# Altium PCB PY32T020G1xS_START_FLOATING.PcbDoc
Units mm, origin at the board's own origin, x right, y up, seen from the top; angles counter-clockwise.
Board outline 150 x 47.08 mm, 2 copper layers (Top Layer, Bottom Layer); 56 components, 46 nets, 145 pads, 14 vias.
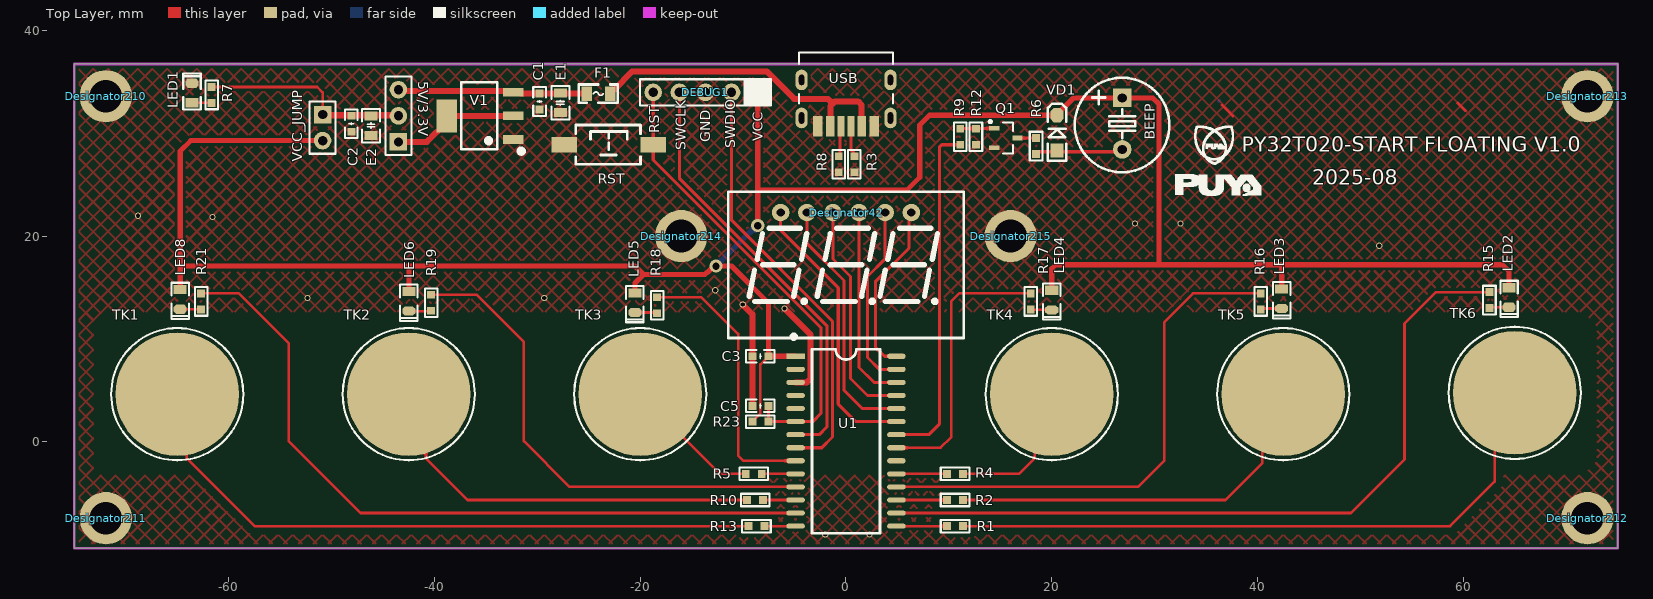
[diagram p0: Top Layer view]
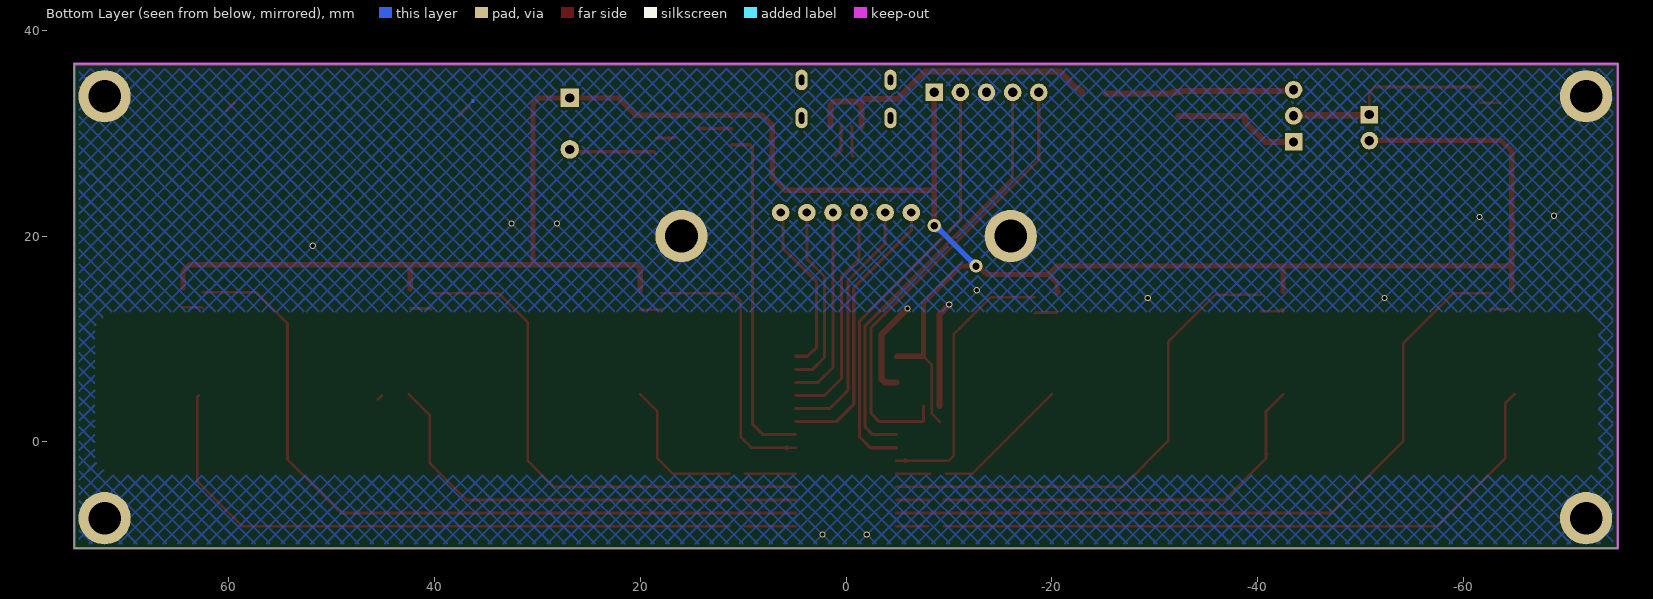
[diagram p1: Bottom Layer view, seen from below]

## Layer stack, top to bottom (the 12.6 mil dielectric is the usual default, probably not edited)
Top Solder: solder mask 0.0102, Solder Resist, Dk 3.5
Top Layer: signal copper 0.0356
Dielectric 1: dielectric 0.32, FR-4, Dk 4.8
Bottom Layer: signal copper 0.0356
Bottom Solder: solder mask 0.0102, Solder Resist, Dk 3.5

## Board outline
-74.993,-10.351 -74.993,36.728 75.006,36.728 75.006,-10.351

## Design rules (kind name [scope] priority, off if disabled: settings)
Clearance tk1 [InNet('NetR13_2')] p1: gap=0.7 ignorepadtopadclearanceinfootprint=FALSE
Clearance tk1_5 [InNet('NetR10_2')] p2: gap=0.7 ignorepadtopadclearanceinfootprint=FALSE
Clearance tk1_4 [InNet('NetR5_2')] p3: gap=0.7 ignorepadtopadclearanceinfootprint=FALSE
Clearance tk1_3 [InNet('NetR4_2')] p4: gap=0.7 ignorepadtopadclearanceinfootprint=FALSE
Clearance tk1_2 [InNet('NetR2_2')] p5: gap=0.7 ignorepadtopadclearanceinfootprint=FALSE
Clearance tk1_1 [InNet('NetR1_2')] p6: gap=0.7 ignorepadtopadclearanceinfootprint=FALSE
Clearance [All] p7: gap=0.254 ignorepadtopadclearanceinfootprint=FALSE
PlaneConnect [All] p1: planeconnectstyle=Direct reliefexpansion=0.508 reliefentries=4 reliefconductorwidth=0.254 reliefairgap=0.254
PolygonConnect [All] p1: connectstyle=Direct reliefconductorwidth=0.254 reliefentries=4 polygonreliefangle="90 Angle" airgapwidth=0.254
RoutingVias [All] p1: holewidth=0.711 width=1.27 viastyle="Through Hole" minholewidth=0.711 minwidth=1.27 maxholewidth=0.711 maxwidth=1.27
SolderMaskExpansion [All] p1: expansion=0.102 istentingtop=FALSE
Width [All] p1: maxlimit=0.6 minlimit=0.254 preferedwidth=0.254
29 further rules are at their usual default settings.

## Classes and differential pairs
component class "PY32T020_Touch Demo5_V1.1": 5V/3.3V BEEP C1 C2 C3 C5 DEBUG1 E1 E2 F1 LED1 LED2 LED3 LED4 LED5 LED6 LED8 Q1 R1 R2 R3 R4 R5 R6 R7 R8 R9 R10 R12 R13 R15 R16 R17 R18 R19 R21 R23 RST TK1 TK2 TK3 TK4 TK5 TK6 U1 USB V1 VCC_JUMP VD1

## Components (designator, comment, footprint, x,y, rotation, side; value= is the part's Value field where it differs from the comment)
5V/3.3V "HDR-1X3" HDR2.54-LI-3P -43.497,31.686 r90 top (schematic designator 1)
BEEP "DC5V" "BEEP 5x9x5.5" 26.86,30.924 r180 top (schematic designator BEEP1)
C1 "104" "C 0603_L" -29.781,33.084 r90 top
C2 "104" "C 0603_L" -48.069,30.924 r90 top
C3 "104" "C 0603_L" -8.319,8.319 r0 top
C5 "104" "C 0603_L" -8.319,3.492 r0 top
DEBUG1 "ISP" ISP_DIP_2.54_5P -8.572,33.972 r180 top
Designator42 "Comment" "SMG 0.36-3P" 0.006,17.209 r0 top
Designator210 "Comment" "M3 125X200"#1 -71.643,33.454 r0 top
Designator211 "Comment" "M3 125X200"#2 -72.024,-7.186 r0 top
Designator212 "Comment" "M3 125X200"#3 71.74,-7.059 r0 top
Designator213 "Comment" "M3 125X200"#4 71.486,33.454 r0 top
Designator214 "Comment" "M3 125X200"#5 -16.779,21.008 r0 top
Designator215 "Comment" "M3 125X200"#6 15.352,43.36 r0 top
E1 "10uF/10V" "C 0805_L" -27.749,32.956 r270 top
E2 "10uF/10V" "C 0805_L" -46.164,30.736 r270 top
F1 "500ma" "FU 0805" -24.066,33.846 r180 top
LED1 "红色" "LED 0805R" -63.564,33.912 r90 top
LED2 "红色" "LED 0805G" 64.453,14.034 r270 top
LED3 "红色" "LED 0805G" 42.355,13.906 r270 top
LED4 "红色" "LED 0805G" 20.002,13.779 r270 top
LED5 "红色" "LED 0805G" -20.511,13.525 r270 top
LED6 "红色" "LED 0805G" -42.481,13.652 r270 top
LED8 "红色" "LED 0805G" -64.706,13.84 r270 top
Q1 "SS8050" SOT23-3L 15.557,29.527 r270 top
R1 "4.3K" "R 0603_L" 10.604,-8.191 r0 top
R2 "4.3K" "R 0603_L" 10.604,-5.651 r0 top
R3 "5.1K" "R 0603_L" 0.826,26.987 r90 top
R4 "4.3K" "R 0603_L" 10.604,-3.111 r0 top
R5 "4.3K" "R 0603_L" -8.954,-3.111 r180 top
R6 "200R" "R 0603_L" 18.479,28.75 r270 top
R7 "1K" "R 0603_L" -61.658,33.718 r90 top
R8 "5.1K" "R 0603_L" -0.699,26.987 r90 top
R9 "1K" "R 0603_L" 11.112,29.654 r270 top
R10 "4.3K" "R 0603_L" -8.826,-5.651 r180 top
R12 "10K" "R 0603_L" 12.636,29.654 r90 top
R13 "4.3K" "R 0603_L" -8.7,-8.191 r180 top
R15 "1K" "R 0603_L" 62.547,13.779 r90 top
R16 "1K" "R 0603_L" 40.322,13.652 r90 top
R17 "1K" "R 0603_L" 17.97,13.652 r90 top
R18 "1K" "R 0603_L" -18.351,13.271 r90 top
R19 "1K" "R 0603_L" -40.322,13.525 r90 top
R21 "1K" "R 0603_L" -62.674,13.652 r90 top
R23 "10K" "R 0603_L" -8.319,1.968 r180 top
RST "6x6x5" "TSW SMD-3*6*5" -23.05,28.892 r0 top (schematic designator RST1)
TK1 "Touch 10X10mm" Touch-12X12mm -64.993,4.635 r0 top (schematic designator Th7)
TK2 "Touch 10X10mm" Touch-12X12mm -42.494,4.635 r0 top (schematic designator Th5)
TK3 "Touch 10X10mm" Touch-12X12mm -19.994,4.635 r0 top (schematic designator Th4)
TK4 "Touch 10X10mm" Touch-12X12mm 20.007,4.635 r0 top (schematic designator Th3)
TK5 "Touch 10X10mm" Touch-12X12mm 42.506,4.635 r0 top (schematic designator Th2)
TK6 "Touch 10X10mm" Touch-12X12mm 65.006,4.763 r0 top (schematic designator Th1)
U1 "PY32T020G16" SOP28_L 0.006,0.064 r0 top
USB "USB-C" USB-C/S_C 0.006,37.728 r180 top (schematic designator USB_POWER1)
V1 "AMS1117-3V3" SOT223_N -35.623,31.686 r90 top
VCC_JUMP "HDR-1X2" HDR2.54-LI-2P -50.863,30.543 r270 top (schematic designator VCC_JUMP1)
VD1 "A7" SOD-123 20.511,30.035 r90 top

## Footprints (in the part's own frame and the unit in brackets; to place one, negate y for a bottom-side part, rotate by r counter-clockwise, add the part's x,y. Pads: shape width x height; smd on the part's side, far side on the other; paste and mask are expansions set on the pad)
"BEEP 5x9x5.5" [mm] "5*9*5.5mm(脚距,直径,高度)"
  rect 1.8x1.8 hole 0.9: 1(0,-2.5)
  round 1.8 hole 0.9: 2(0,2.5)
  silkscreen extent -4.58,-4.47 4.62,4.72, body extent -4.5,-4.5 4.5,4.5, height 5.45
"C 0603_L" [mil] "无极性贴片电容"
  rect 30x30 smd: 1(-30.59,0) 2(30.59,0)
  silkscreen extent -55,-24 55,24, body extent -31,-16 31,16, height 32
"C 0805_L" [mil] "无极性贴片电容"
  rect 35x50 smd: 1(-37.4,0) 2(37.4,0)
  silkscreen extent -64,-34 64,34, body extent -39,-24 39,24, height 20
"FU 0805" [mil] "贴片保险丝"
  rect 40x55 smd: 1(-45,0) 2(45,0)
  silkscreen extent -75,-35 75,35, body extent -39,-24 39,24, height 20
HDR2.54-LI-2P [mm] "排针，2脚"
  rect 1.7x1.7 hole 0.9: 1(-1.27,0)
  round 1.7 hole 0.9: 2(1.27,0)
  silkscreen extent -2.54,-1.27 2.54,1.27, body extent -2.54,-1.27 2.54,1.27, height 8.5
HDR2.54-LI-3P [mm] "排针，3脚"
  rect 1.7x1.7 hole 0.9: 1(-2.54,0)
  round 1.7 hole 0.9: 2(0,0) 3(2.54,0)
  silkscreen extent -3.81,-1.27 3.81,1.27, body extent -3.81,-1.27 3.81,1.27, height 8.5
ISP_DIP_2.54_5P [mm] "5P 下载端口"
  rect 1.7x1.7 hole 0.9: 1(0,0)
  round 1.7 hole 0.9: 2(2.54,0) 3(5.08,0) 4(7.62,0) 5(10.16,0)
  silkscreen extent -1.27,-1.27 11.43,1.27
"LED 0805G" [mil] "绿色0805LED"
  rect 35x50 smd: 1(-37.4,0)
  oct 35x50 smd: 2(37.4,0)
  silkscreen extent -64,-33 75,33, body extent -39,-25 39,25, height 32
"LED 0805R" [mil] "红色0805LED"
  rect 35x50 smd: 1(-37.41,0)
  oct 35x50 smd: 2(37.4,0)
  silkscreen extent -64,-33 75,33, body extent -39,-25 39,25, height 32
"M3 125X200"#1 [mm] "M3螺丝孔，孔125Mil，焊盘200Mil"
  round 5.08 hole 3.175: 1(-0.287,0.132)
"M3 125X200"#2 [mm] "M3螺丝孔，孔125Mil，焊盘200Mil"
  round 5.08 hole 3.175: 1(0.094,-0.228)
"M3 125X200"#3 [mm] "M3螺丝孔，孔125Mil，焊盘200Mil"
  round 5.08 hole 3.175: 1(0.33,-0.355)
"M3 125X200"#4 [mm] "M3螺丝孔，孔125Mil，焊盘200Mil"
  round 5.08 hole 3.175: 1(0.584,0.132)
"M3 125X200"#5 [mm] "M3螺丝孔，孔125Mil，焊盘200Mil"
  round 5.08 hole 3.175: 1(0.779,-1.008)
"M3 125X200"#6 [mm] "M3螺丝孔，孔125Mil，焊盘200Mil"
  round 5.08 hole 3.175: 1(0.648,-23.36)
"R 0603_L" [mil] "1/10W贴片电阻"
  rect 30x30 smd: 1(-30.59,0) 2(30.59,0)
  silkscreen extent -55,-24 55,24, body extent -31,-16 32,16, height 16
"SMG 0.36-3P" [mm] "22.5*14*7.2mm(长宽厚)"
  round 1.7 hole 0.8: 7(6.35,5.08) 8(3.81,5.08) 9(1.27,5.08) 10(-1.27,5.08) 11(-3.81,5.08) 12(-6.35,5.08)
  silkscreen extent -11.43,-7.11 11.43,7.11, body extent -11.25,-7 11.25,7, height 7.2
SOD-123 [mil] "2.7x1.6X1.1mm（长宽高，不包括引脚）"
  rect 55x50 smd: 1(-67.5,0)
  oct 55x50 smd: 2(67.5,0)
  silkscreen extent -108,-35 112,35, body extent -73,-31 73,31, height 48
SOP28_L [mm] "17.9*10.6*2.6mm（长宽高）"
  rect 1.8x0.5 smd: 1(-4.9,8.255)
  oval 1.8x0.5 smd: 2(-4.9,6.985) 3(-4.9,5.715) 4(-4.9,4.445) 5(-4.9,3.175) 6(-4.9,1.905) 7(-4.9,0.635) 8(-4.9,-0.635) 9(-4.9,-1.905) 10(-4.9,-3.175) 11(-4.9,-4.445) 12(-4.9,-5.715) 13(-4.9,-6.985) 14(-4.9,-8.255) 15(4.9,-8.255) 16(4.9,-6.985) 17(4.9,-5.715) 18(4.9,-4.445) 19(4.9,-3.175) 20(4.9,-1.905) 21(4.9,-0.635) 22(4.9,0.635) 23(4.9,1.905) 24(4.9,3.175) 25(4.9,4.445) 26(4.9,5.715) 27(4.9,6.985) 28(4.9,8.255)
  silkscreen extent -5.23,-8.95 3.3,10.31, body extent -5.15,-8.95 5.15,8.95, height 2.7
SOT23-3L [mm] "3x1.3x1mm(长宽高)"
  rect 0.45x1 smd: 1(-0.95,-1.143) 2(0.95,-1.143) 3(0,1.125)
  silkscreen extent -1.72,-1.65 1.5,0.7, body extent -1.5,-1.2 1.5,1.2, height 1.05
SOT223_N [mm] "6.4x7x1.6mm(长宽高)"
  rect 0.85x2 smd: 1(-2.3,-3.302) 2(0,-3.302) 3(2.3,-3.302)
  rect 3.2x2 smd: 2(0,3.175)
  silkscreen extent -3.63,-4.26 3.25,1.75, body extent -3.25,-3.51 3.25,3.51, height 1.65
Touch-12X12mm [mm] "触摸焊盘12mm*12mm"
  round 12 smd paste-12 mask+0.5: Touch(0,0)
  silkscreen extent -6.42,-6.42 6.42,6.42
"TSW SMD-3*6*5" [mm] "3*6*5mm"
  rect 2.5x1.5 smd: 1(-4.318,0) 2(4.318,0)
  silkscreen extent -3.21,-1.9 3.09,1.9, body extent -4.6,-1.75 4.6,1.75, height 5.1
USB-C/S_C [mm] "Type-C 6P母座"
  oval 1.2x2 hole 0.5 slot 1.1 at 90 deg: 0(-4.32,6.25) 0(4.32,6.25)
  oval 1.2x2 hole 0.5 slot 1 at 90 deg: 0(-4.32,2.55) 0(4.32,2.55)
  rect 0.7x2 smd: A5(-0.5,7.05) B5(0.5,7.05)
  rect 0.8x2 smd: A9(1.52,7.05) B9(-1.52,7.05)
  rect 0.9x2 smd: A12(2.75,7.05) B12(-2.75,7.05)
  silkscreen extent -4.57,-0.13 4.57,4.83, body extent -4.47,0 4.48,7.05, height 3.16

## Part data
5V/3.3V: library part "Header 3", "3P接插件"
BEEP: library part BEEP, "蜂鸣器"
C1 C2 C3 C5: library part C, "无极性贴片电容"
DEBUG1: library part ISP_5Pin, "程序下载端口"
E1 E2: library part C-CM, "贴片电解电容"
F1: library part FU, "贴片保险丝"
LED1 LED2 LED3 LED4 LED5 LED6 LED8: library part LED-SMD, "贴片LED"
Q1: library part 8050-DIP, "高频放大-NPN型"
R1 R2 R4 R5 R6 R7 R9 R10 R12 R13 R15 R16 R17 R18 R19 R21 R23: library part R, "贴片电阻"
R3 R8: library part R
RST: library part "TSW DIP-2Pin-6x6", "2脚直插6x6轻触开关"
TK1 TK2 TK3 TK4 TK5 TK6: library part Touch-1P, "触控焊盘"
USB: library part USB-C_6P/S, "USB-C_6P型母接口"
V1: library part AMS1117, "三端稳压芯片"
VCC_JUMP: library part "Header 2", "2P接插件"
VD1: library part DIODE

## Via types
v1: diameter 0.6, hole 0.4, Top Layer to Bottom Layer, 12 vias
v2: diameter 1.27, hole 0.711, Top Layer to Bottom Layer, 2 vias

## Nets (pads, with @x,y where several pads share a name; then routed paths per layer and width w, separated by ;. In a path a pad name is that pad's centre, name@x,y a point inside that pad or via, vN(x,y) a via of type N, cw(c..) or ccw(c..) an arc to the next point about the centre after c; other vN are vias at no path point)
BEEP: R9.2 U1.22 | length 33.6
  Top Layer w0.3: U1.22 8.064,0.699 9.08,1.714 9.08,28.639 9.319,28.877 R9.2
GND: C1.1 C2.1 C3.1 C5.1 DEBUG1.3 Designator210.1 Designator211.1 Designator212.1 Designator213.1 Designator214.1 Designator215.1 E1.2 E2.2 LED1.2 Q1.2 R3.1 R8.1 R12.1 RST.1 U1.3 USB.A12 USB.B12 V1.1 | length 22.2
  Top Layer w0.254: 36.548,32.736 37.613,31.672
  Top Layer w0.3: 59.468,32.93 60.196,32.203
  Top Layer w0.6: v1(-10.033,13.335) -9.096,12.398 C3.1 C5.1 ; v1(-5.969,12.954) -3.44,10.425 -3.44,6.13 -3.791,5.779 U1.3
  other v1: -2.014,-9.011 2.304,-9.011 -52.324,13.97 -29.319,13.976 -12.7,14.732 51.834,19.056 28.085,21.215 32.53,21.215 -61.577,21.85 -68.816,21.977
LED1: R15.2 U1.16 | length 74.3
  Top Layer w0.254: U1.16 49.085,-6.921 54.292,-1.714 54.292,11.493 57.356,14.557 R15.2
LED2: R17.2 U1.21 | length 27
  Top Layer w0.254: U1.21 9.207,-0.572 10.223,0.445 10.223,13.652 11.001,14.43 R17.2
LED3: R19.2 U1.11 | length 48.8
  Top Layer w0.254: R19.2 -35.893,14.303 -31.305,9.716 -31.305,0.064 -26.86,-4.381 U1.11
LED4: R21.2 U1.13 | length 72.2
  Top Layer w0.254: R21.2 -59.007,14.43 -54.165,9.588 -54.165,0.064 -47.18,-6.921 U1.13
LED5: R16.2 U1.18 | length 51.1
  Top Layer w0.254: U1.18 28.384,-4.381 30.924,-1.841 30.924,11.62 33.734,14.43 R16.2
LED6: R18.2 U1.9 | length 27
  Top Layer w0.254: R18.2 -14.049,14.049 -10.477,10.477 -10.477,-1.333 -9.97,-1.841 U1.9
Net1_1: 5V/3.3V.1 V1.2 | length 12.6
  Top Layer w0.6: 5V/3.3V.1 -40.738,29.146 -38.798,31.086 -38.798,31.686 V1.2@-32.322,31.686
Net1_2: 5V/3.3V.2 C2.2 E2.1 R7.2 VCC_JUMP.1 | length 20.6
  Top Layer w0.254: R7.2 -51.387,34.496 -50.863,33.972 VCC_JUMP.1
  Top Layer w0.6: VCC_JUMP.1 -50.8,31.75 -43.561,31.75 5V/3.3V.2
NetBEEP1_2: BEEP.2 R6.2 VD1.1 | length 8.6
  Top Layer w0.3: R6.2 18.704,28.199 26.635,28.199 BEEP.2
NetLED1_1: LED1.1 R7.1 | length 1.9
  Top Layer w0.254: LED1.1 -61.678,32.961 R7.1
NetLED2_2: LED2.2 R15.1 | length 1.9
  Top Layer w0.254: R15.1 62.629,13.084 LED2.2
NetLED3_2: LED3.2 R16.1 | length 2.1
  Top Layer w0.254: R16.1 40.404,12.957 LED3.2
NetLED4_2: LED4.2 R17.1 | length 2.1
  Top Layer w0.254: R17.1 18.016,12.83 LED4.2
NetLED5_2: LED5.2 R18.1 | length 2.2
  Top Layer w0.254: LED5.2 -18.433,12.576 R18.1
NetLED6_2: LED6.2 R19.1 | length 2.4
  Top Layer w0.254: LED6.2 -42.482,12.763 -42.355,12.89 -42.167,12.703 -40.368,12.703 R19.1
NetLED8_2: LED8.2 R21.1 | length 2
  Top Layer w0.254: LED8.2 -62.69,12.89 R21.1
NetQ1_1: Q1.1 R9.1 R12.2 | length 3.3
  Top Layer w0.3: R9.1 11.135,30.455 14.392,30.455 Q1.1
NetQ1_3: Q1.3 R6.1 | length 1.8
  Top Layer w0.3: Q1.3 R6.1
NetR1_2: R1.2 TK6.Touch | length 61.9
  Top Layer w0.254: R1.2 58.737,-8.191 63.055,-3.873 63.055,4.381 TK6.Touch@62.928,4.508
NetR2_2: R2.2 TK5.Touch | length 38.7
  Top Layer w0.254: R2.2 36.893,-5.651 40.45,-2.095 40.45,2.579 TK5.Touch ; TK5.Touch@45.13,4.508 TK5.Touch@45.511,4.127
NetR3_2: R3.2 USB.A5 | length 3.2
  Top Layer w0.3: USB.A5 0.506,28.338 R3.2@1.079,27.765
NetR4_2: R4.2 TK4.Touch | length 14.5
  Top Layer w0.254: R4.2 16.828,-3.111 18.342,-1.597 18.342,2.971 TK4.Touch
NetR5_2: R5.2 TK3.Touch | length 13.5
  Top Layer w0.254: TK3.Touch -12.247,-3.111 R5.2
NetR8_2: R8.2 USB.B5 | length 3
  Top Layer w0.3: R8.2 -0.596,27.867 -0.596,30.576 USB.B5
NetR10_2: R10.2 TK2.Touch | length 39.9
  Top Layer w0.254: TK2.Touch -40.821,2.963 -40.821,-1.597 -36.766,-5.651 R10.2@-9.477,-5.651
NetR13_2: R13.2 TK1.Touch | length 63.9
  Top Layer w0.254: TK1.Touch -64.062,3.704 -64.062,-1.597 -57.468,-8.191 R13.2
NRST: C5.2 DEBUG1.5 R23.1 RST.2 U1.6 | length 44.9
  Top Layer w0.3: DEBUG1.5 RST.2 -18.732,27.389 -2.408,11.064 -2.408,2.799 -3.238,1.968 U1.6 R23.1 C5.2
SEGA: Designator42.12 U1.23 | length 27.3
  Top Layer w0.3: Designator42.12 -6.344,20.568 -0.746,14.97 -0.746,3.667 0.953,1.968 U1.23
SEGB: Designator42.11 U1.24 | length 24.6
  Top Layer w0.3: Designator42.11 -3.804,19.298 -0.191,15.684 -0.191,5.016 1.587,3.238 U1.24
SEGC: Designator42.10 U1.25 | length 22
  Top Layer w0.3: Designator42.10 -1.264,17.774 0.445,16.066 0.445,6.159 2.095,4.508 U1.25
SEGD: Designator42.9 U1.26 | length 19.3
  Top Layer w0.3: Designator42.9 1.276,7.233 2.73,5.779 U1.26
SEGE: Designator42.8 U1.27 | length 18.1
  Top Layer w0.3: Designator42.8 3.816,17.786 2.095,16.066 2.095,8.191 3.238,7.048 U1.27
SEGF: Designator42.7 U1.28 | length 16.9
  Top Layer w0.3: U1.28 3.746,8.319 2.857,9.207 2.857,15.557 6.13,18.83 6.13,22.062 Designator42.7
SWCLK: DEBUG1.4 U1.7 | length 41.8
  Top Layer w0.3: DEBUG1.4 -16.192,25.632 -1.854,11.293 -1.854,1.448 -2.603,0.699 U1.7
SWDIO: DEBUG1.2 U1.8 | length 41.6
  Top Layer w0.3: DEBUG1.2 -11.112,21.526 -1.3,11.714 -1.3,0.478 -2.349,-0.572 U1.8
TK1: R1.1 U1.15 | length 4.9
  Top Layer w0.254: U1.15 R1.1
TK2: R4.1 U1.19 | length 4.9
  Top Layer w0.254: U1.19 R4.1
TK3: R10.1 U1.12 | length 3.2
  Top Layer w0.254: R10.1 R10.1@-7.922,-5.779
  Top Layer w0.3: R10.1@-7.922,-5.651 -7.795,-5.651 U1.12
TK4: R13.1 U1.14 | length 3
  Top Layer w0.254: R13.1 U1.14
TK5: R2.1 U1.17 | length 4.9
  Top Layer w0.254: U1.17 R2.1
TK6: R5.1 U1.10 | length 3.3
  Top Layer w0.254: R5.1 U1.10
V5V: 5V/3.3V.3 C1.2 E1.1 F1.2 V1.3 | length 18.4
  Top Layer w0.6: 5V/3.3V.3 -43.378,34.107 -32.441,34.107 V1.3 -31.746,33.987 -31.605,33.846 F1.2
VBUS: F1.1 USB.A9 USB.B9 | length 31.3
  Top Layer w0.6: F1.1 -22.924,34.036 -22.715,34.244 -22.525,34.244 -20.767,36.002 -7.681,36.002 -5.016,33.337 -1.768,33.337 -1.297,32.866 ; USB.A9 -1.514,32.649 -1.297,32.866 ; USB.B9 1.526,32.732 1.175,33.084 -1.079,33.084 -1.297,32.866
VCC: BEEP.1 C3.2 DEBUG1.1 LED2.1 LED3.1 LED4.1 LED5.1 LED6.1 LED8.1 R23.2 U1.1 VCC_JUMP.2 VD1.2 | length 238
  Top Layer w0.254: R23.2 -8.318,2.746 -8.318,7.542 C3.2
  Top Layer w0.5: LED8.1 -64.706,16.828 ; VCC_JUMP.2 -63.691,29.273 -64.706,28.258 -64.706,16.828 ; LED6.1 -42.481,17.081 ; LED5.1@-20.637,14.603 LED5.1 -20.511,15.43 -19.685,16.256 ; v2(-8.572,21.018) -8.572,24.447 ; DEBUG1.1 -8.572,24.447 ; U1.1 C3.2 -7.541,13.51 -11.112,17.081 v2(-12.636,17.081) -12.845,17.081 -13.416,16.51 -13.462,16.51 -13.716,16.256 -19.685,16.256 ; LED4.1 20.002,16.827 20.383,17.209 30.543,17.209 ; LED3.1 42.354,17.208 ; LED2.1 64.452,16.574 63.817,17.209 42.355,17.209 ; -64.706,16.828 -64.453,17.081 -42.481,17.081 ; -42.481,17.081 -20.511,17.081 -19.685,16.256 ; -8.572,24.447 5.905,24.447 7.175,25.717 7.175,30.797 8.128,31.75 VD1.2 20.511,31.813 22.122,33.425 BEEP.1 29.821,33.425 30.416,32.829 30.416,17.335 30.543,17.209 ; 30.543,17.209 42.355,17.209
  Bottom Layer w0.5: v2(-12.636,17.081) -8.7,21.018 v2(-8.572,21.018)
pads on no net: U1.2 U1.4 U1.5 U1.20 USB.0

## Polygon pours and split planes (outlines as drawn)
GND on Bottom Layer "GND_L02_P000" (hatched 45Degree grid 1.016 track 0.203, remove dead copper, pour order 0): -75.12,36.767 -74.867,36.512 -74.867,-10.351 74.867,-10.351 74.993,-10.223 74.993,36.893
GND on Top Layer "GND_L01_P001" (hatched 45Degree grid 1.016 track 0.203, remove dead copper, pour order 1): -75.184,36.703 -74.93,36.449 -74.93,-10.414 74.803,-10.414 74.93,-10.287 74.93,36.83

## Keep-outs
Keep-Out Layer:
  the board outline again, w0.254

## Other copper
Top Layer:
  pour cut-out: 60.557,-0.802 ccw(c65.125,5.099) 70.827,0.284 ccw(c65.161,4.758)
  pour cut-out: 37.748,-0.963 ccw(c42.316,4.938) 48.018,0.124 ccw(c42.352,4.598)
  pour cut-out: 15.396,-0.836 ccw(c19.964,5.065) 25.666,0.251 ccw(c20,4.725)
  pour cut-out: -24.736,-0.963 ccw(c-20.168,4.938) -14.466,0.124 ccw(c-20.132,4.598)
  pour cut-out: -47.342,-0.963 ccw(c-42.774,4.938) -37.072,0.124 ccw(c-42.738,4.598)
  pour cut-out: -69.567,-0.963 ccw(c-64.999,4.938) -59.297,0.124 ccw(c-64.963,4.598)
  pour cut-out: -73.088,-2.54 -72.453,-3.175 71.628,-3.175 72.962,-1.842 72.962,11.239 71.628,12.573 -72.2,12.573 -73.088,11.684
Bottom Layer:
  pour cut-out: 60.602,10.45 cw(c65.17,4.549) 70.872,9.364 cw(c65.206,4.89)
  pour cut-out: 37.875,10.234 cw(c42.443,4.333) 48.145,9.147 cw(c42.479,4.673)
  pour cut-out: 15.396,10.234 cw(c19.964,4.333) 25.666,9.147 cw(c20,4.673)
  pour cut-out: -24.609,9.98 cw(c-20.041,4.079) -14.339,8.893 cw(c-20.005,4.419)
  pour cut-out: -47.342,10.234 cw(c-42.774,4.333) -37.072,9.147 cw(c-42.738,4.673)
  pour cut-out: -69.567,10.234 cw(c-64.999,4.333) -59.297,9.147 cw(c-64.963,4.673)
  pour cut-out: -73.088,-2.54 -72.453,-3.175 71.628,-3.175 72.962,-1.842 72.962,11.239 71.628,12.573 -72.2,12.573 -73.088,11.684

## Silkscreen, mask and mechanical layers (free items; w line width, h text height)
Top Overlay:
  drawing of 1057 lines, arcs and shapes, not listed
  text "RST" at -18.161,29.972 h1 r90
  text "VCC" at -8.097,29.225 h1 r90
  text "GND" at -13.177,29.098 h1 r90
  text "SWDIO" at -10.779,28.539 h1 r90
  text "SWCLK" at -15.59,28.336 h1 r90
  text "PY32T020-START FLOATING V1.0" at 38.484,27.717 h2.48
  text "2025-08" at 45.337,24.491 h2.48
